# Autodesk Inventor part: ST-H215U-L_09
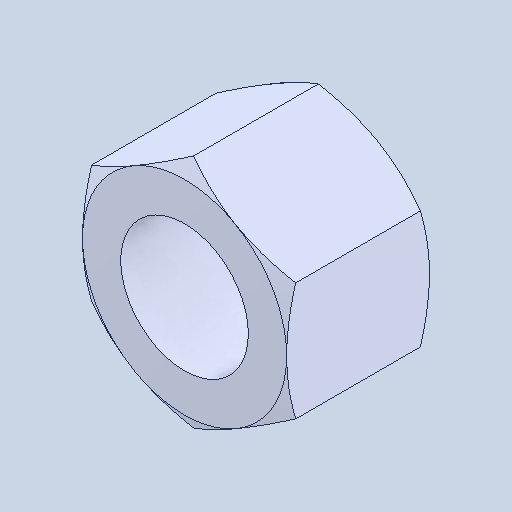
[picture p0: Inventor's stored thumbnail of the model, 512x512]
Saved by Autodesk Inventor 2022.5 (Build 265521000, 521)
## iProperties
Created: 2024-07
Part Number: ST-H215U-L_09
Material: 一般
Document SubType Name: Modeling
Designer: ImaoCorp
Density: 1 g/cm^3
Appearance: 既定
Author: ImaoCorp
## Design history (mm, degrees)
feature "ST-H215U-L_09"
node "ソリッド1"
